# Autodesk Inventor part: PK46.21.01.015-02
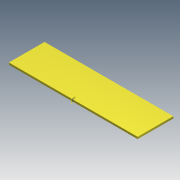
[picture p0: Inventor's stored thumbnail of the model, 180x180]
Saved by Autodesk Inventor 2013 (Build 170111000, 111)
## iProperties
Created: 2005-04
Part Number: PK46.21.01.015-02
Material: Steel, Mild
Document SubType Name: Modeling
Designer: salex
Manufacturer: Standard
Standards Organization: Custom
Density: 7.86 g/cm^3
Author: salex
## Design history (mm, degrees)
sketch "Эскиз1"
  geometry: L1 (0, 0)-(650, 0); L2 (650, 0)-(650, 180); L3 (650, 180)-(0, 180); L4 (0, 180)-(0, 0)
  constraints: 8 end point, 2 parallel, 1 horizontal, 1 perpendicular, 1 other
  dimensions: "d0" = 180 distance of L3.end L1.start; "d1" = 650 distance of L1.start L1.end
extrude "Выдавливание1" new body sketch "Эскиз1" distance "d2" = 10; taper "d3" = 0 deg
node "РабПлоскость1"
body "Solid1"
